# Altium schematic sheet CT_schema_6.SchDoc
size 372 x 335 mm
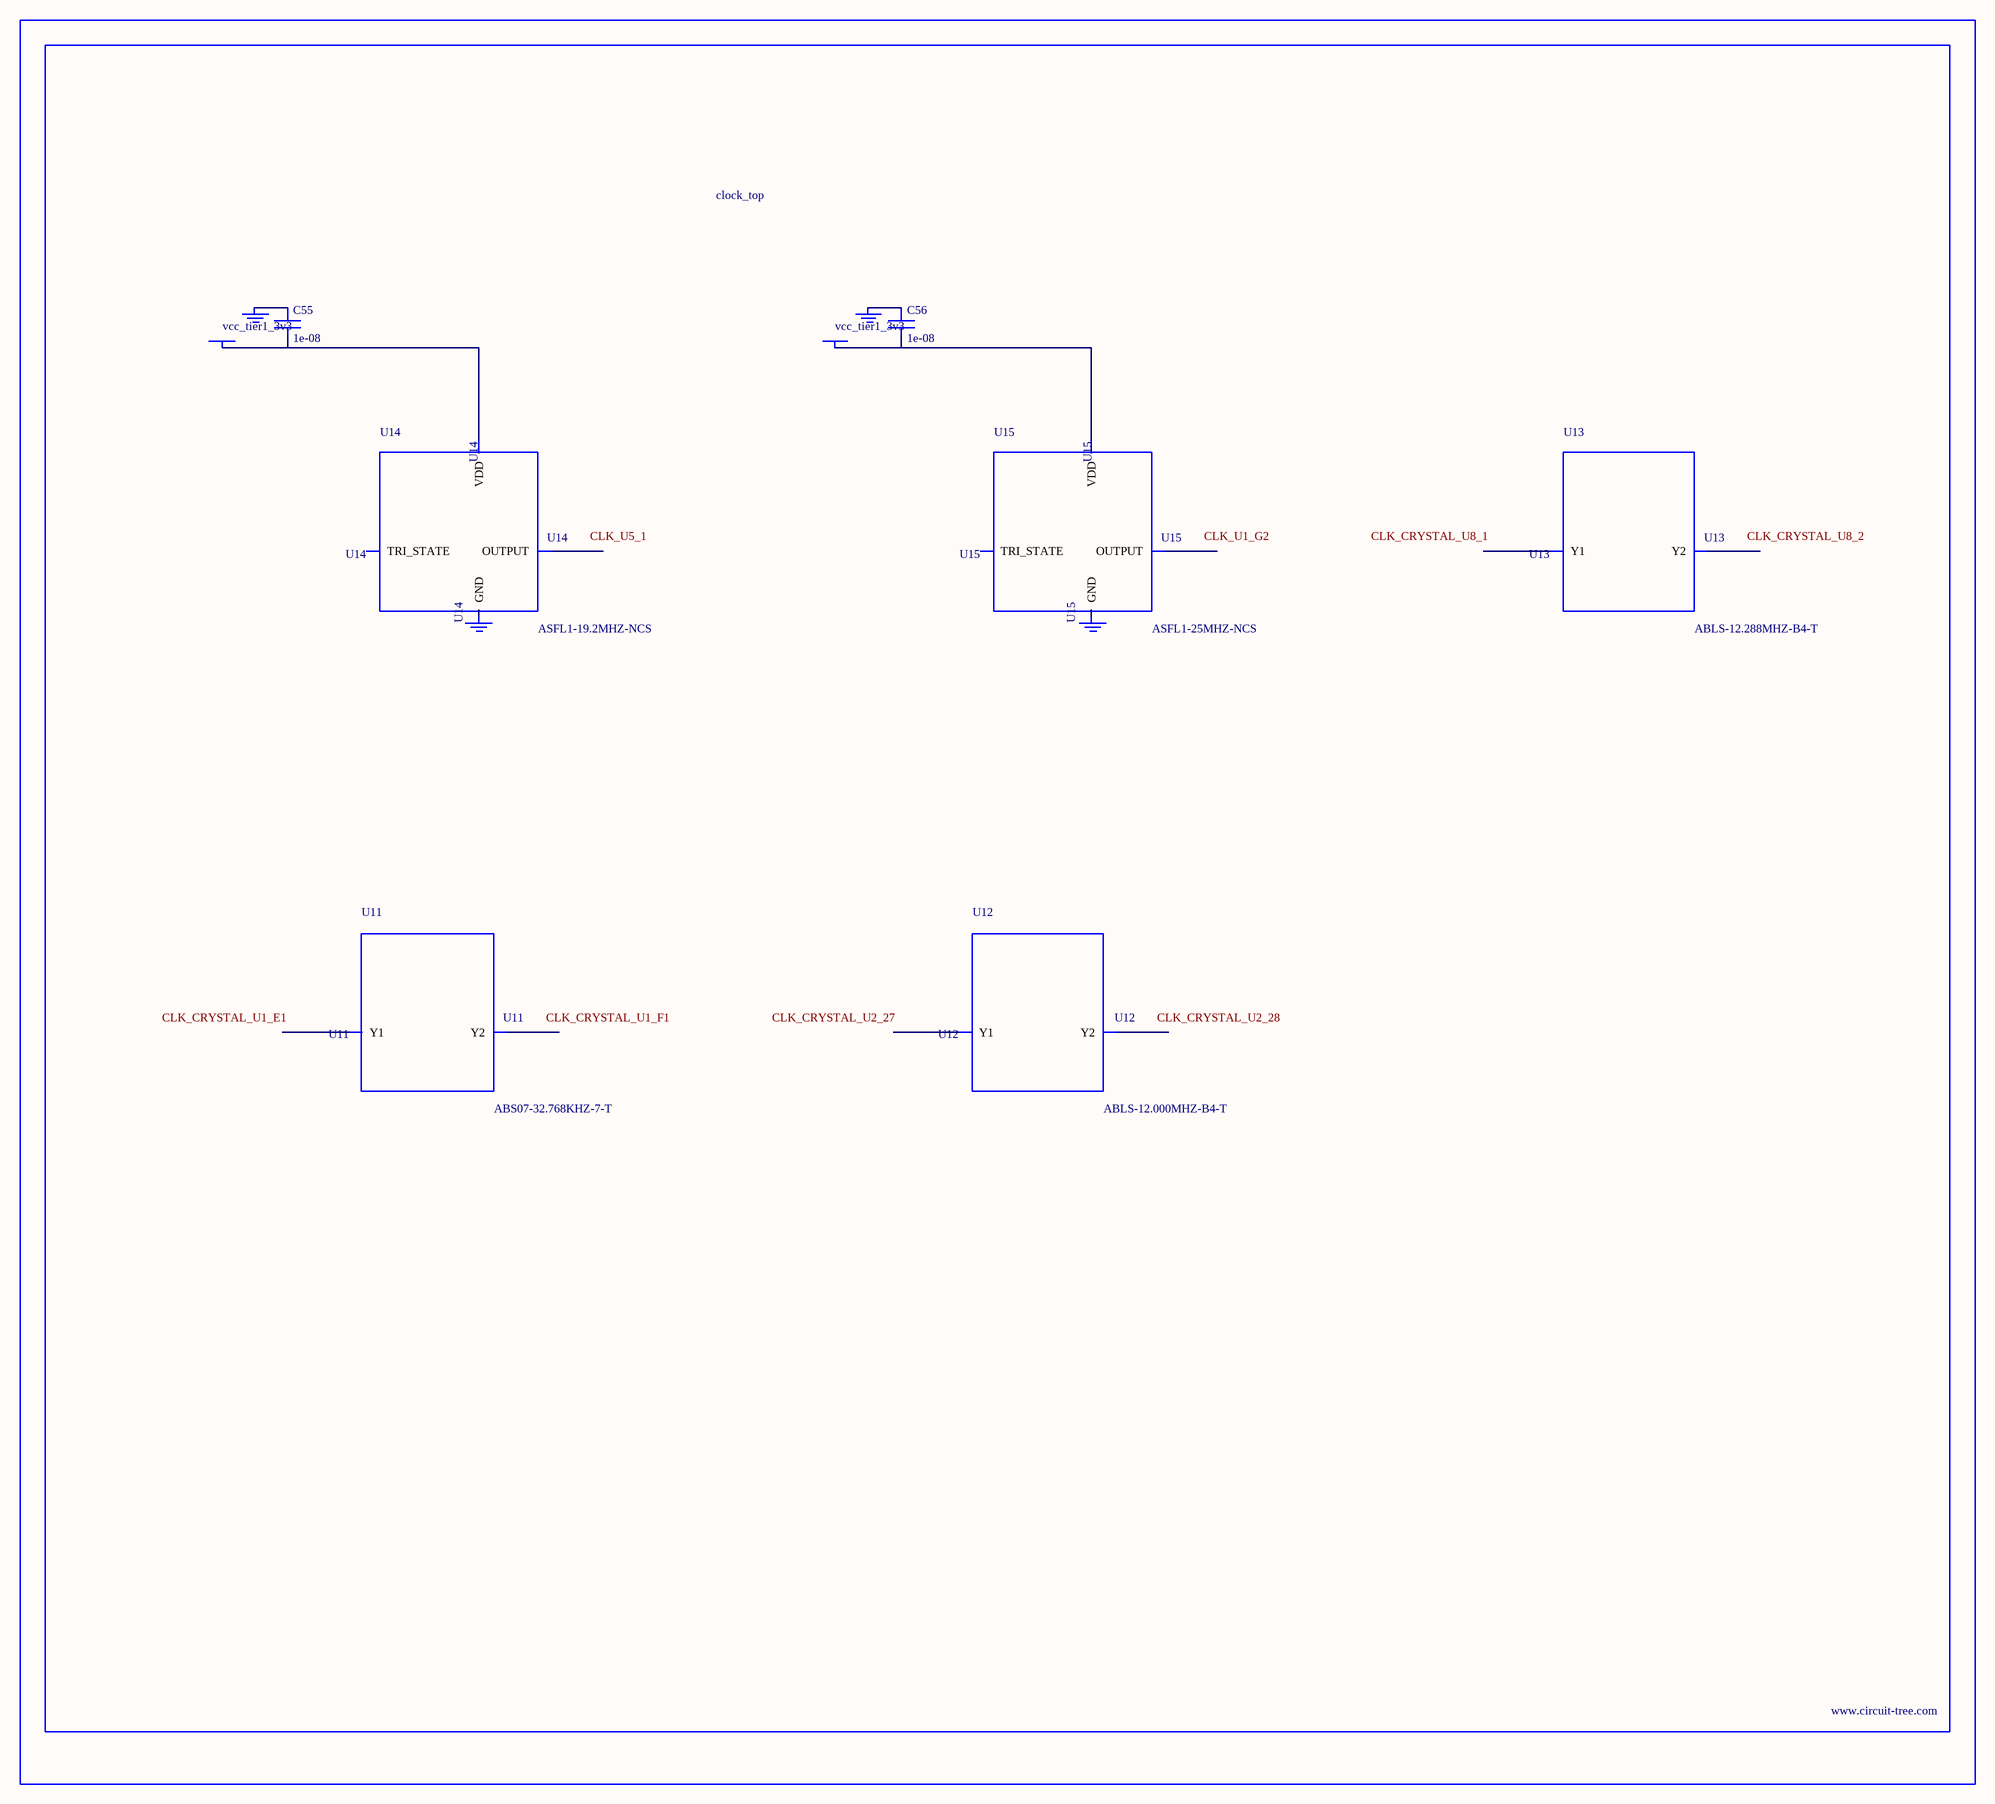
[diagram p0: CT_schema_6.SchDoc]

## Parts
BORDER5  (no value)
C55  1e-08  [C0402]
C56  1e-08  [C0402]
GND_INSTANCE_5_0  (no value)
GND_INSTANCE_5_1  (no value)
GND_INSTANCE_5_2  (no value)
GND_INSTANCE_5_3  (no value)
POWER_INSTANCE_5_0  vcc_tier1_3v3
POWER_INSTANCE_5_1  vcc_tier1_3v3
U11  ABS07-32.768KHZ-7-T  [ABS07-32.768KHZ-7-T]
U12  ABLS-12.000MHZ-B4-T  [ABLS-12.000MHZ-B4-T]
U13  ABLS-12.288MHZ-B4-T  [ABLS-12.288MHZ-B4-T]
U14  ASFL1-19.2MHZ-NCS  [ASFL1]
U15  ASFL1-25MHZ-NCS  [ASFL1]

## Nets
NetC55_1: C55.1 GND_INSTANCE_5_0.0(GND)
NetC55_2: C55.2 POWER_INSTANCE_5_0.0(PWR) U14.4(VDD)
NetC56_1: C56.1 GND_INSTANCE_5_2.0(GND)
NetC56_2: C56.2 POWER_INSTANCE_5_1.0(PWR) U15.4(VDD)

Not connected (* = marked no-connect by the designer): GND_INSTANCE_5_1 0(GND); GND_INSTANCE_5_3 0(GND); U11 1(Y1) 2(Y2); U12 1(Y1) 2(Y2); U13 1(Y1) 2(Y2); U14 1(TRI_STATE) 2(GND) 3(OUTPUT); U15 1(TRI_STATE) 2(GND) 3(OUTPUT)

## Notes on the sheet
- Labels drawn without touching a wire or pin: CLK_CRYSTAL_U1_E1, CLK_CRYSTAL_U1_F1, CLK_CRYSTAL_U2_27, CLK_CRYSTAL_U2_28, CLK_CRYSTAL_U8_1, CLK_CRYSTAL_U8_2, CLK_U1_G2, CLK_U5_1

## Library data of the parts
BORDER5 = BORDER_PAGE5
C55 C56 = C0402C103K3RAC
GND_INSTANCE_5_0-GND_INSTANCE_5_3 = GND
POWER_INSTANCE_5_0 POWER_INSTANCE_5_1 = PWR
